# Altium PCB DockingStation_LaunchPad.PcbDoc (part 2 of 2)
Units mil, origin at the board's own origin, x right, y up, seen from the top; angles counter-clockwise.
Board outline 5425 x 6950 mil, 4 copper layers (Top Layer, GND, Power, Bottom Layer), stack 58.4 mil thick; 172 components, 183 nets, 692 pads, 746 vias.
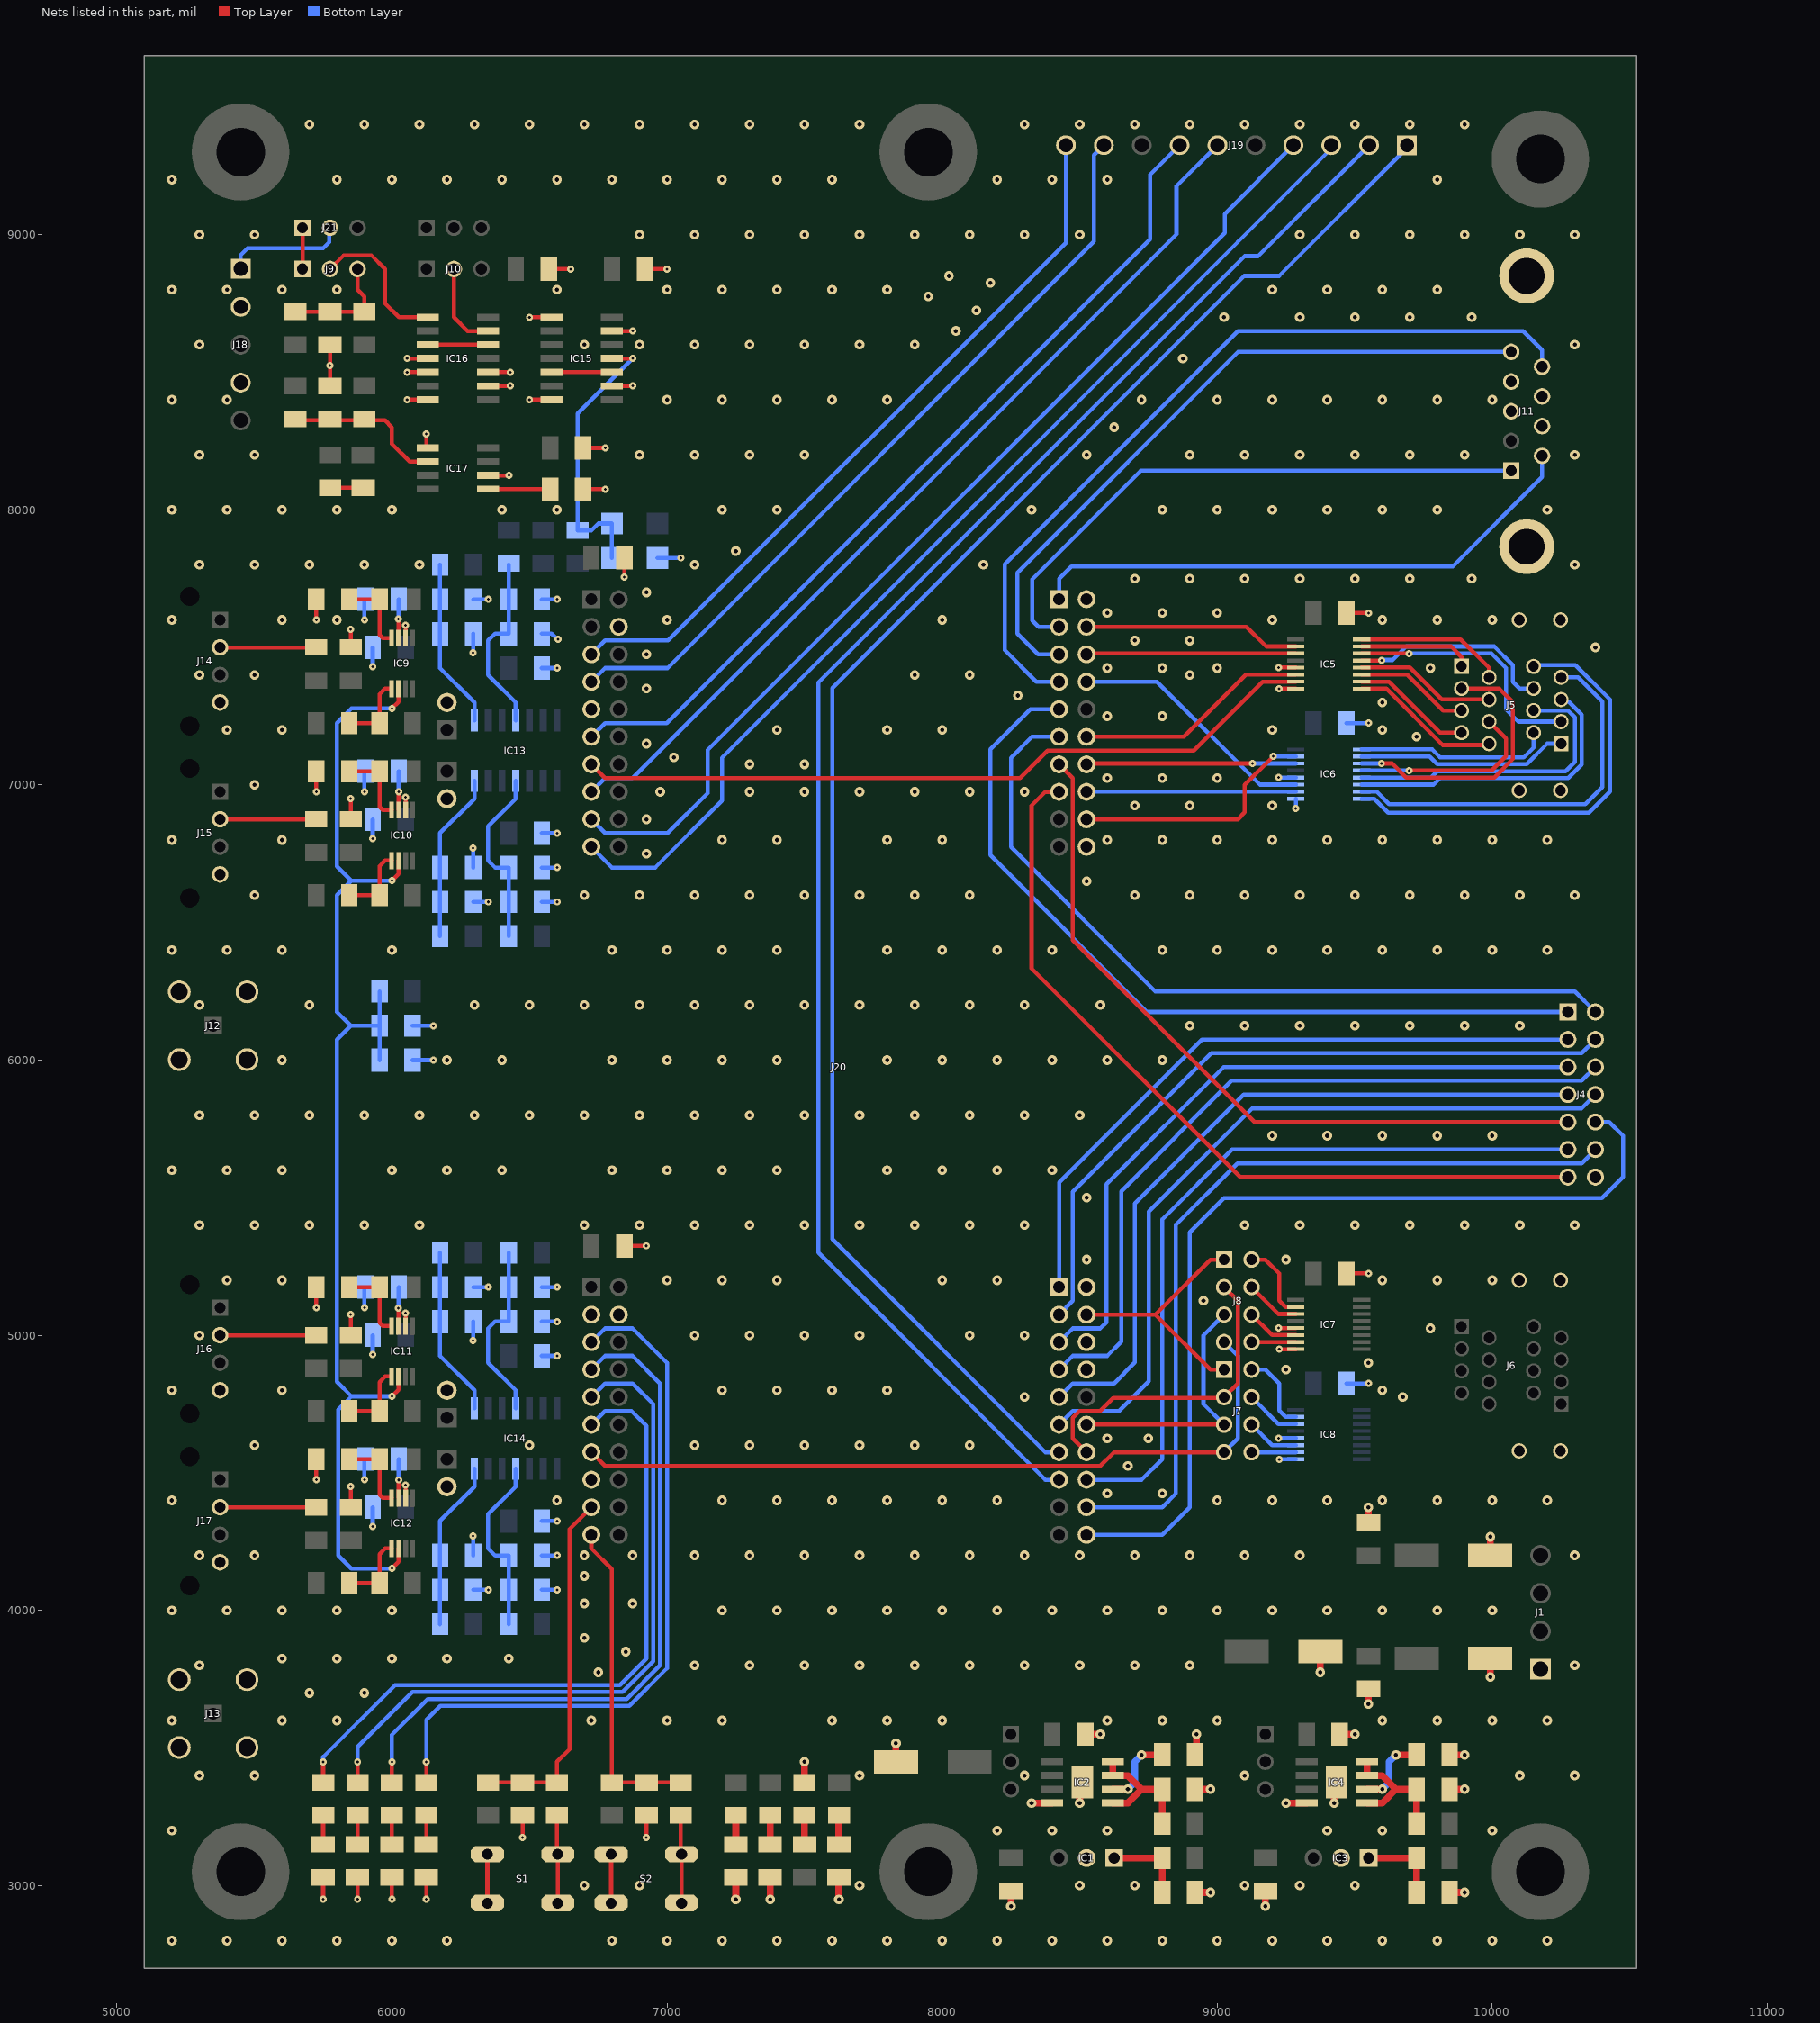
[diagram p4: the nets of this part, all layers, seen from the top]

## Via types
v1: diameter 35, hole 15, Top Layer to Bottom Layer, tented both sides, 433 vias
v2: diameter 35, hole 15, Top Layer to Bottom Layer, tented top, 166 vias
v3: diameter 26, hole 10, Top Layer to Bottom Layer, tented top, 146 vias
v4: diameter 26, hole 10, Top Layer to Bottom Layer, tented both sides, 1 vias

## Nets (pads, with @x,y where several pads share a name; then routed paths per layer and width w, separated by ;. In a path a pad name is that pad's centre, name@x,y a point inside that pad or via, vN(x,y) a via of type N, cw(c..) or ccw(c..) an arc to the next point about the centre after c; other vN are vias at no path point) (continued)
GND: +3.3V.1 +5V.1 +15V.1 C1_1.2 C2_1.2 C2_2.2 C2_3.2 C2_4.2 C3.1 C4.1 C5.2 C6.2 C8.2 C9.2 C10.2 C11.2 C12.2 C14.2 C16.2 C17.2 C18.2 C19.2 C20.2 C22.2 C23.2 C24.2 C25.2 C26.2 C27.2 C28.2 C29.2 C30.2 C31.2 C32.2 C33.2 C34.1 C35.2 C36.1 C37.2 C38.2 C39.2 C40.2 C41.2 C42.2 C43.2 C44.2 Cn_1.2 Cn_2.2 Cn_3.2 Cn_4.2 Cp_1.2 Cp_2.2 Cp_3.2 Cp_4.2 D2.2 IC1.2 IC2.4 IC2.9 IC3.2 IC4.4 IC4.9 IC5.5 IC5.8 IC6.9 IC6.12 IC7.5 IC7.8 IC8.9 IC8.12 IC9.6 IC10.6 IC11.6 IC12.6 IC15.1 IC15.7 IC15.9 IC15.13 IC16.4 IC16.5 IC16.7 IC16.9 IC16.10 IC17.1 IC17.6 J1.1 J4.14 J5.18 J5.19 J5.20 J5.21 J6.18 J6.19 J6.20 J6.21 J11.3 J11.4 J11.7 J11.8 J11.10 J12.2 J12.3 J12.4 J12.5 J13.2 J13.3 J13.4 J13.5 J14.3 J15.3 J16.3 J17.3 J18.2 J18.4 J20.20 J20.22 J20.60 J20.62 LED_0.1 LED_1.1 LED_2.1 LED_3.1 R2.2 R3_1.2 R3_2.2 R3_3.2 R3_4.2 R6_1.2 Rm_1.2 Rm_2.2 Rm_3.2 Rm_4.2 Rn2_1.1 Rn2_2.1 Rn2_3.1 Rn2_4.1 Rp2_1.1 Rp2_2.1 Rp2_3.1 Rp2_4.1 S1.3 S1.4 S2.3 S2.4 T1.2 T2.2 T3.2 T4.2 | length 7417.3
  Top Layer w15: v3(5725,4475) R3_4.2@5725,4550 ; v3(5725,5100) R3_3.2@5725,5175 ; v3(5725,6975) R3_2.2@5725,7050 ; v3(5725,7600) R3_1.2@5725,7675 ; v3(5750,2950) LED_3.1@5750,3030 ; C32.2@5775,8450 v3(5775,8525) C31.2@5775,8600 ; Rm_4.2@5850,4375 v3(5850,4450) ; Rm_3.2@5850,5000 v3(5850,5075) ; Rm_2.2@5850,6875 v3(5850,6950) ; Rm_1.2@5850,7500 v3(5850,7565) ; v3(5875,2950) LED_2.1@5875,3030 ; v3(6000,2950) LED_1.1@6000,3030 ; IC11.6@6049.41,5033.5 6050,5034.09 v3(6050,5080) ; IC9.6@6049.41,7533.5 6050,7534.09 v3(6050,7580) ; IC12.6@6050,4408.5 v3(6050,4455) ; IC10.6@6050,6908.5 v3(6050,6955) ; v3(6055,8400) IC16.7@6130,8400 ; v3(6055,8500) IC16.5@6130,8500 ; v3(6055,8550) IC16.4@6130,8550 ; v3(6125,2950) LED_0.1@6125,3030 ; v3(6125,8275) 6125,8230 IC17.1@6130,8225 ; S1.3@6347,2936 S1.4@6347,3114 ; IC17.6@6350,8125 v3(6425,8125) ; IC16.9@6350,8450 v3(6430,8450) ; IC16.10@6350,8500 v3(6430,8500) ; v3(6475,3175) C41.2@6475,3255 ; v3(6500,8400) IC15.7@6580,8400 ; v3(6500,8700) IC15.1@6580,8700 ; C38.2@6570,8875 v3(6650,8875) ; C40.2@6695,8075 v3(6775,8075) ; C39.2@6695,8225 v3(6775,8225) ; S2.3@6797,2936 S2.4@6797,3114 ; IC15.9@6800,8450 v3(6875,8450) ; IC15.13@6800,8650 v3(6875,8650) ; C44.2@6845,5325 v3(6925,5325) ; v3(6845,7755) C43.2@6845,7825 ; C37.2@6920,8875 v3(7000,8875) ; v3(6925,3175) C42.2@6925,3255 ; v3(9223.23,7426.77) IC5.5@9285.5,7426.77 ; v3(9223.82,5026.18) IC7.5@9285.5,5026.18 ; v3(9225,7350) IC5.8@9285.5,7350 ; v3(9225.59,4949.41) IC7.8@9285.5,4949.41 ; C25.2@9470,5225 v3(9550,5225) ; C23.2@9470,7625 v3(9550,7625)
  Top Layer w25: v2(7250,2950) +3.3V.1@7250,3030 ; v2(7375,2950) +5V.1@7375,3030 ; R2.2@7500,3375 v2(7500,3450) ; v2(7625,2950) +15V.1@7625,3030 ; C14.2@7832.28,3450 v2(7832.28,3517.72) ; v2(8250,2925) C9.2@8250,2980 ; v2(8325,3300) IC2.4@8400,3300 ; v2(8500,3300) 8500,3365.43 IC2.9@8509.76,3375.2 ; C12.2@8520,3550 v2(8575,3550) ; C8.2@8920,2975 v2(8975,2975) ; C10.2@8920,3350 v2(8975,3350) ; C11.2@8920,3475 8925,3480 v2(8925,3550) ; v2(9175,2925) C17.2@9175,2980 ; v2(9250,3300) IC4.4@9325,3300 ; v2(9375,3775) C22.2@9375,3850 ; v2(9425,3300) 9425,3365.43 IC4.9@9434.76,3375.2 ; C20.2@9445,3550 v2(9500,3550) ; v2(9550,3660) C5.2@9550,3715 ; C3.1@9550,4320 v2(9550,4375) ; C16.2@9845,2975 v2(9900,2975) ; C18.2@9845,3350 v2(9900,3350) ; C19.2@9845,3475 v2(9900,3475) ; v2(9992.72,3757.28) C6.2@9992.72,3825 ; C4.1@9992.72,4200 v2(9992.72,4267.72)
  Bottom Layer w15: v3(5900,4475) 5900,4545 C2_4.2@5905,4550 ; v3(5900,5100) 5900,5170 C2_3.2@5905,5175 ; v3(5900,6975) 5900,7045 C2_2.2@5905,7050 ; v3(5900,7600) 5900,7670 C2_1.2@5905,7675 ; v3(5930,4305) C30.2@5930,4375 ; v3(5930,4930) C29.2@5930,5000 ; v3(5930,6805) C28.2@5930,6875 ; v3(5930,7430) C27.2@5930,7500 ; C1_1.2@6075,6000 v3(6150,6000) ; R6_1.2@6075,6125 v3(6150,6125) ; Rp2_4.1@6295,4075 v3(6350,4075) ; Cp_4.2@6295,4200 v3(6295,4270) ; v3(6295,4980) Cn_3.2@6295,5050 ; Rn2_3.1@6295,5175 v3(6350,5175) ; Rp2_2.1@6295,6575 v3(6350,6575) ; Cp_2.2@6295,6700 v3(6295,6770) ; v3(6295,7480) Cn_1.2@6295,7550 ; Rn2_1.1@6295,7675 v3(6350,7675) ; Rn2_4.1@6545,4075 v3(6600,4075) ; Cn_4.2@6545,4200 v3(6600,4200) ; C35.2@6545,4325 v3(6600,4325) ; C36.1@6545,4925 v3(6600,4925) ; Cp_3.2@6545,5050 v3(6600,5050) ; Rp2_3.1@6545,5175 v3(6600,5175) ; Rn2_2.1@6545,6575 v4(6600,6575) ; Cn_2.2@6545,6700 v3(6600,6700) ; C33.2@6545,6825 v3(6600,6825) ; C34.1@6545,7425 v3(6600,7425) ; Cp_1.2@6545,7550 6580.46,7550 6600.96,7529.5 v3(6603.94,7529.5) ; Rp2_1.1@6545,7675 v3(6600,7675) ; D2.2@6965.35,7825 v3(7050,7825) ; v3(9223.23,7026.77) IC6.12@9285.5,7026.77 ; v3(9223.82,4626.18) IC8.12@9285.5,4626.18 ; v3(9225.59,4549.41) IC8.9@9285.5,4549.41 ; v3(9285.5,6914.5) IC6.9@9285.5,6950 ; C26.2@9470,4825 v3(9550,4825) ; C24.2@9470,7225 v3(9550,7225)
  other v1: 5200,2800 5400,2800 5600,2800 5800,2800 6000,2800 6200,2800 6800,2800 7000,2800 7200,2800 7400,2800 7600,2800 7800,2800 8000,2800 8200,2800 8400,2800 8600,2800 8800,2800 9000,2800 9200,2800 9400,2800 9600,2800 9800,2800 10000,2800 10200,2800 6700,3000 6900,3000 7700,3000 8500,3000 8700,3000 9100,3000 9300,3000 9500,3000 5200,3200 8200,3200 8400,3200 8600,3200 9400,3200 9600,3200 10000,3200 5300,3400 5500,3400 7700,3400 8300,3400 9100,3400 10100,3400 10300,3400 5200,3600 5600,3600 5800,3600 7000,3600 7200,3600 7600,3600 7800,3600 8000,3600 8600,3600 8800,3600 9000,3600 9600,3600 9800,3600 10000,3600 10200,3600 5300,3800 7100,3800 7300,3800 7500,3800 7700,3800 7900,3800 8100,3800 8300,3800 8500,3800 8700,3800 8900,3800 10300,3800 5200,4000 5400,4000 5600,4000 5800,4000 6000,4000 7200,4000 7400,4000 7600,4000 7800,4000 8000,4000 8200,4000 8400,4000 8600,4000 8800,4000 9000,4000 9200,4000 9400,4000 9600,4000 9800,4000 10000,4000 5300,4200 5500,4200 6700,4200 7100,4200 7300,4200 7500,4200 7700,4200 7900,4200 8100,4200 8300,4200 8500,4200 8700,4200 8900,4200 9100,4200 9300,4200 10300,4200 5200,4400 6600,4400 7200,4400 7400,4400 7600,4400 7800,4400 8000,4400 8200,4400 9000,4400 9200,4400 9400,4400 9600,4400 9800,4400 10000,4400 10200,4400 5500,4600 6500,4600 7100,4600 7300,4600 7500,4600 7700,4600 7900,4600 8100,4600 5200,4800 5600,4800 7200,4800 7400,4800 7600,4800 7800,4800 9600,4800 5300,5000 7100,5000 7300,5000 7500,5000 7700,5000 8100,5000 8300,5000 5400,5200 5600,5200 7000,5200 7200,5200 7400,5200 8000,5200 8200,5200 9600,5200 9800,5200 10000,5200 5300,5400 5500,5400 5700,5400 5900,5400 6100,5400 6700,5400 6900,5400 7100,5400 7300,5400 7500,5400 7700,5400 7900,5400 8100,5400 8300,5400 9100,5400 9300,5400 9500,5400 9700,5400 9900,5400 10100,5400 10300,5400 5200,5600 5400,5600 5600,5600 6000,5600 6200,5600 6400,5600 6800,5600 7000,5600 7200,5600 7400,5600 7800,5600 8000,5600 8200,5600 8400,5600 5300,5800 5500,5800 5700,5800 5900,5800 6100,5800 6300,5800 6500,5800 6700,5800 6900,5800 7100,5800 7300,5800 7500,5800 7700,5800 7900,5800 8100,5800 8300,5800 8500,5800 5600,6000 6200,6000 6400,6000 6800,6000 7000,6000 7200,6000 7400,6000 7800,6000 8000,6000 8200,6000 8400,6000 8600,6000 8800,6000 5300,6200 5700,6200 6300,6200 6500,6200 6700,6200 6900,6200 7100,6200 7300,6200 7500,6200 7700,6200 7900,6200 8100,6200 8300,6200 5200,6400 5400,6400 5600,6400 6000,6400 6800,6400 7000,6400 7200,6400 7400,6400 7800,6400 8000,6400 8200,6400 8400,6400 8800,6400 9000,6400 9200,6400 9400,6400 9600,6400 9800,6400 10000,6400 10200,6400 5500,6600 6700,6600 6900,6600 7100,6600 7300,6600 7500,6600 7700,6600 7900,6600 8100,6600 8700,6600 8900,6600 9100,6600 9300,6600 9500,6600 9700,6600 9900,6600 10100,6600 10300,6600 5200,6800 5600,6800 7200,6800 7400,6800 7800,6800 8000,6800 8600,6800 8800,6800 9000,6800 9200,6800 9400,6800 9600,6800 9800,6800 10000,6800 10200,6800 5500,7000 5400,7200 5600,7200 7400,7200 7800,7200 8000,7200 9200,7200 9600,7200 5300,7400 5500,7400 7900,7400 8100,7400 8900,7400 5200,7600 5600,7600 5800,7600 7000,7600 8000,7600 9200,7600 9600,7600 9800,7600 10000,7600 5300,7800 5500,7800 5700,7800 5900,7800 6100,7800 7100,7800 10300,7800 5200,8000 5400,8000 5600,8000 5800,8000 6000,8000 6400,8000 6600,8000 7200,8000 7400,8000 8800,8000 9000,8000 9200,8000 9400,8000 9600,8000 9800,8000 10200,8000 5300,8200 5500,8200 6900,8200 7100,8200 7300,8200 7500,8200 8900,8200 9100,8200 9300,8200 9500,8200 9700,8200 9900,8200 10300,8200 5200,8400 5400,8400 7000,8400 7200,8400 7400,8400 7600,8400 7800,8400 9000,8400 9200,8400 9400,8400 9600,8400 9800,8400 10000,8400 5300,8600 6700,8600 6900,8600 7100,8600 7300,8600 7500,8600 7700,8600 7900,8600 10300,8600 5200,8800 5400,8800 5600,8800 5800,8800 6600,8800 7000,8800 7200,8800 7400,8800 7600,8800 7800,8800 9200,8800 9400,8800 9600,8800 9800,8800 5300,9000 5500,9000 6900,9000 7100,9000 7300,9000 7500,9000 7700,9000 7900,9000 8100,9000 8300,9000 8500,9000 9300,9000 9500,9000 9700,9000 9900,9000 10100,9000 10300,9000 5200,9200 5800,9200 6000,9200 6200,9200 6400,9200 6600,9200 6800,9200 7000,9200 7200,9200 7400,9200 7600,9200 8200,9200 8400,9200 8600,9200 9800,9200 5700,9400 5900,9400 6100,9400 6300,9400 6500,9400 6700,9400 6900,9400 7100,9400 7300,9400 7500,9400 7700,9400 8300,9400 8500,9400 8700,9400 8900,9400 9100,9400 9300,9400 9500,9400 9700,9400 9900,9400
  other v2: 6725,3600 5700,3700 5900,3700 6750,3775 5600,3825 5800,3825 6000,3825 6200,3825 6425,3825 6850,3850 6700,3900 6700,4025 6875,4025 6700,4125 6875,4200 8600,4425 8800,4425 8675,4525 8600,4625 8750,4625 8300,4775 9675,4775 9250,4875 9550,4900 9775,5025 8950,5125 8525,5275 9250,5275 8525,5500 9200,5725 9400,5725 9600,5725 9800,5725 10000,5725 8900,6125 9100,6125 9300,6125 9500,6125 9700,6125 9900,6125 10100,6125 8575,6200 8525,6650 6925,6750 6925,6875 8700,6925 8900,6925 9200,6925 6975,6975 7300,6975 7500,6975 7700,6975 7900,6975 8100,6975 8300,6975 8600,7025 8800,7025 9000,7025 7300,7075 7500,7075 7025,7100 6925,7150 9725,7175 8600,7250 8800,7250 9600,7300 8275,7325 6925,7350 8600,7425 8800,7425 9000,7425 9775,7425 6925,7475 10375,7500 8700,7525 8900,7525 8600,7625 8800,7625 9000,7625 6925,7700 8700,7750 8900,7750 9100,7750 9300,7750 9500,7750 9700,7750 9925,7750 8150,7800 7250,7850 8325,8000 8525,8200 8625,8300 8725,8400 8875,8550 8050,8650 9025,8700 9300,8700 9500,8700 9700,8700 9925,8700 8125,8725 7950,8775 8175,8825 8025,8850
GPIO_COM0: J4.1 J20.36 | length 3030.9
  Bottom Layer w15: J20.36@8425,7275 8320.38,7275 8175,7129.62 8175,6745.08 8745.08,6175 J4.1@10275,6175
GPIO_COM1: J4.2 J20.35 | length 2903.6
  Bottom Layer w15: J20.35@8425,7175 8326.71,7175 8250,7098.29 8250,6775 8775,6250 10300,6250 J4.2@10375,6175
GPIO_COM2: J4.3 J20.80 | length 2445.5
  Bottom Layer w15: J20.80@8425,5175 8425,5555.19 8944.81,6075 J4.3@10275,6075
GPIO_COM3: J4.4 J20.79 | length 2596.5
  Bottom Layer w15: J20.79@8425,5075 8475.02,5125.02 8475.02,5521.57 8978.45,6025 10325,6025 J4.4@10375,6075
GPIO_COM4: J4.5 J20.78 | length 2557.9
  Bottom Layer w15: J20.78@8425,4975 8475,5025 8575,5025 8597.53,5047.53 8597.53,5548.97 9023.56,5975 J4.5@10275,5975
GPIO_COM5: J4.6 J20.77 | length 2726.4
  Bottom Layer w15: J20.77@8425,4875 8475,4925 8600,4925 8651.08,4976.08 8651.08,5523.58 9052.5,5925 10325,5925 J4.6@10375,5975
GPIO_COM6: J4.7 J20.76 | length 2644.3
  Bottom Layer w15: J20.76@8425,4775 8475.02,4825.02 8625.02,4825.02 8700.98,4900.98 8700.98,5479.07 9096.91,5875 J4.7@10275,5875
GPIO_COM7: J4.8 J20.75 | length 2808.3
  Bottom Layer w15: J20.75@8425,4675 8475,4725 8643.8,4725 8751.5,4832.7 8751.5,5449.41 9127.09,5825 10325,5825 J4.8@10375,5875
GPIO_COM8: J4.9 J20.34 | length 2733.6
  Top Layer w15: J20.34@8425,7075 8475,7025 8475,6435.79 9135.79,5775 J4.9@10275,5775
GPIO_COM9: J4.10 J20.51 | length 3344.4
  Bottom Layer w15: J20.51@8525,4275 8800,4275 8900,4375 8900,5373.97 9024.73,5498.69 10398.69,5498.69 10475,5575 10475,5725 10425,5775 J4.10@10375,5775
GPIO_COM10: J4.11 J20.53 | length 2757.2
  Bottom Layer w15: J20.53@8525,4475 8725,4475 8800,4550 8800,5420.93 9054.07,5675 J4.11@10275,5675
GPIO_COM11: J4.12 J20.52 | length 2960.5
  Bottom Layer w15: J20.52@8525,4375 8800,4375 8850,4425 8850,5401.58 9073.42,5625 10325,5625 J4.12@10375,5675
GPIO_COM12: J4.13 J20.33 | length 2976.8
  Top Layer w15: J20.33@8425,6975 8375,6975 8325,6925 8325,6332.74 9082.74,5575 J4.13@10275,5575
Master_Enable: J9.1 J21.1 | length 150.5
  Top Layer w15: J9.1@5675,8875 5674.41,8875.59 5675,8876.18 J21.1@5675,9025
MCLK+: IC5.10 J5.A7 | length 440
  Top Layer w15: IC5.10@9525,7375.59 9624.41,7375.59 9809.84,7190.16 J5.A7@9888.19,7190.16
MCLK-: IC5.9 J5.A8 | length 550.1
  Top Layer w15: IC5.9@9525,7350 9614.64,7350 9819.55,7145.1 9983.29,7145.1 J5.A8@9988.19,7150
MI+: IC6.3 J5.A3 | length 1013.1
  Top Layer w15: v3(9597.05,7077.95) 9635.73,7077.95 9686.82,7026.86 10007.49,7026.86 10075,7094.37 10075,7300.79 10025,7350.79 J5.A3@9888.19,7350.79
  Bottom Layer w15: IC6.3@9525,7077.95 v3(9597.05,7077.95)
MI-: IC6.4 J5.A6 | length 697.9
  Top Layer w15: v3(9697.64,7052.36) 9997.64,7052.36 10050,7104.72 10050,7168.5 J5.A6@9988.19,7230.31
  Bottom Layer w15: IC6.4@9525,7052.36 v3(9697.64,7052.36)
MO+: IC5.11 J5.A5 | length 417.3
  Top Layer w15: IC5.11@9525,7401.18 9690.24,7401.18 9820.94,7270.47 J5.A5@9888.19,7270.47
MO-: IC5.12 J5.A4 | length 522
  Top Layer w15: IC5.12@9525,7426.77 9700,7426.77 9816.14,7310.63 J5.A4@9988.19,7310.63 J5.A4@9980.61,7318.21
MSS+: IC5.15 J5.A1 | length 413.3
  Top Layer w15: IC5.15@9525,7503.54 9850,7503.54 9888.19,7465.35 J5.A1@9888.19,7431.1
MSS-: IC5.16 J5.A2 | length 541.2
  Top Layer w15: IC5.16@9525,7529.13 9885.43,7529.13 9988.19,7426.38 J5.A2@9988.19,7390.94
Net+3.3V_2: +3.3V.2 R5.2 | length 105
  Top Layer w25: +3.3V.2@7250,3150 R5.2@7250,3255
Net+5V_2: +5V.2 R4.2 | length 105
  Top Layer w25: +5V.2@7375,3150 R4.2@7375,3255
Net+15V_2: +15V.2 R3.2 | length 105
  Top Layer w25: +15V.2@7625,3150 R3.2@7625,3255
Net-15V_2: -15V.2 R2.1 | length 105
  Top Layer w25: -15V.2@7500,3150 R2.1@7500,3255
NetC2_1_1: C2_1.1 IC9.7 | length 142
  Top Layer w15: IC9.7@6023.82,7533.5 v3(6023.82,7603.82)
  Bottom Layer w15: v3(6023.82,7603.82) 6023.82,7673.82 C2_1.1@6025,7675
NetC2_2_1: C2_2.1 IC10.7 | length 141.7
  Top Layer w15: IC10.7@6024.41,6908.5 v3(6024.41,6974.41)
  Bottom Layer w15: v3(6024.41,6974.41) 6024.41,7049.41 C2_2.1@6025,7050
NetC2_3_1: C2_3.1 IC11.7 | length 142
  Top Layer w15: IC11.7@6023.82,5033.5 v3(6023.82,5098.82)
  Bottom Layer w15: v3(6023.82,5098.82) 6023.82,5173.82 C2_3.1@6025,5175
NetC2_4_1: C2_4.1 IC12.7 | length 141.7
  Top Layer w15: IC12.7@6024.41,4408.5 v3(6024.41,4474.41)
  Bottom Layer w15: v3(6024.41,4474.41) 6024.41,4549.41 C2_4.1@6025,4550
NetC8_1: C8.1 IC1.1 R6.2 | length 300
  Top Layer w25: IC1.1@8625,3100 R6.2@8800,3100 C8.1@8800,2975
NetC10_1: C10.1 IC2.5 IC2.7 IC2.8 R7.1 | length 501.4
  Top Layer w25: IC2.5@8620,3300 8675,3300 8725,3350 ; IC2.8@8620,3450 IC2.7@8620,3400 8675,3400 8725,3350 ; R7.1@8800,3225 C10.1@8800,3350 8725,3350
NetC11_1: C11.1 IC2.6 | length 275.7
  Top Layer w25: IC2.6@8620,3350 v2(8675,3350) ; v2(8725,3475) C11.1@8800,3475
  Bottom Layer w25: v2(8675,3350) 8700,3375 8700,3450 v2(8725,3475)
NetC16_1: C16.1 IC3.1 R8.2 | length 300
  Top Layer w25: IC3.1@9550,3100 R8.2@9725,3100 C16.1@9725,2975
NetC18_1: C18.1 IC4.5 IC4.7 IC4.8 R9.1 | length 501.4
  Top Layer w25: IC4.5@9545,3300 9600,3300 9650,3350 ; IC4.8@9545,3450 IC4.7@9545,3400 9600,3400 9650,3350 ; R9.1@9725,3225 C18.1@9725,3350 9650,3350
NetC19_1: C19.1 IC4.6 | length 275.7
  Top Layer w25: IC4.6@9545,3350 v2(9600,3350) ; v2(9650,3475) C19.1@9725,3475
  Bottom Layer w25: v2(9600,3350) 9625,3375 9625,3450 v2(9650,3475)
NetC40_1: C40.1 IC17.5 | length 225
  Top Layer w15: IC17.5@6350,8075 C40.1@6575,8075
NetCn_1_1: Cn_1.1 IC13.8 Rn1_1.1 Rn2_1.2 | length 616.8
  Bottom Layer w15: Rn1_1.1@6175,7800 Rn2_1.2@6175,7675 Cn_1.1@6175,7550 6175,7425 6300,7300 IC13.8@6300,7235
NetCn_2_1: Cn_2.1 IC13.4 Rn1_2.1 Rn2_2.2 | length 666.8
  Bottom Layer w15: Rn1_2.1@6425,6450 Rn2_2.2@6425,6575 Cn_2.1@6425,6700 6375,6700 6350,6725 6350,6850 6450,6950 IC13.4@6450,7015
NetCn_3_1: Cn_3.1 IC14.8 Rn1_3.1 Rn2_3.2 | length 616.8
  Bottom Layer w15: Rn1_3.1@6175,5300 Rn2_3.2@6175,5175 Cn_3.1@6175,5050 6175,4925 6300,4800 IC14.8@6300,4735
NetCn_4_1: Cn_4.1 IC14.4 Rn1_4.1 Rn2_4.2 | length 666.8
  Bottom Layer w15: Rn1_4.1@6425,3950 Rn2_4.2@6425,4075 Cn_4.1@6425,4200 6375,4200 6350,4225 6350,4350 6450,4450 IC14.4@6450,4515
NetCp_1_1: Cp_1.1 IC13.11 Rp1_1.1 Rp2_1.2 | length 666.8
  Bottom Layer w15: Rp1_1.1@6425,7800 Rp2_1.2@6425,7675 Cp_1.1@6425,7550 6375,7550 6350,7525 6350,7400 6450,7300 IC13.11@6450,7235
NetCp_2_1: Cp_2.1 IC13.7 Rp1_2.1 Rp2_2.2 | length 616.8
  Bottom Layer w15: Rp1_2.1@6175,6450 Rp2_2.2@6175,6575 Cp_2.1@6175,6700 6175,6712.5 6175,6825 6300,6950 IC13.7@6300,7015
NetCp_3_1: Cp_3.1 IC14.11 Rp1_3.1 Rp2_3.2 | length 666.8
  Bottom Layer w15: Rp1_3.1@6425,5300 Rp2_3.2@6425,5175 Cp_3.1@6425,5050 6375,5050 6350,5025 6350,4900 6450,4800 IC14.11@6450,4735
NetCp_4_1: Cp_4.1 IC14.7 Rp1_4.1 Rp2_4.2 | length 616.8
  Bottom Layer w15: Rp1_4.1@6175,3950 Rp2_4.2@6175,4075 Cp_4.1@6175,4200 6175,4212.5 6175,4325 6300,4450 IC14.7@6300,4515
NetD1_2: D1.2 D2.1 IC15.11 R15.2 | length 1043.2
  Top Layer w15: IC15.11@6800,8550 v3(6875,8550)
  Bottom Layer w15: D2.1@6800,7825 D1.2@6800,7950 6750,7950 6725,7925 R15.2@6675,7925 6675,8350 v3(6875,8550)
NetIC9_1: IC9.1 R1_1.1 R2_1.2 | length 266.1
  Top Layer w15: R1_1.1@5845,7225 R2_1.2@5955,7225 5955,7330 5975,7350 IC9.1@5997.82,7350
NetIC9_8: IC9.8 R3_1.1 R4_1.1 | length 294.3
  Top Layer w15: R3_1.1@5849.48,7670.52 R3_1.1@5845,7675 R4_1.1@5955,7675 5955,7545 5966.5,7533.5 IC9.8@5998.23,7533.5
NetIC10_1: IC10.1 R1_2.1 R2_2.2 | length 267.1
  Top Layer w15: R1_2.1@5845,6600 R2_2.2@5955,6600 5955,6705 5975,6725 IC10.1@5998.82,6725
NetIC10_8: IC10.8 R3_2.1 R4_2.1 | length 288.6
  Top Layer w15: R3_2.1@5845,7050 R4_2.1@5955,7050 5955,6920 5966.5,6908.5 IC10.8@5998.82,6908.5
NetIC11_1: IC11.1 R1_3.1 R2_3.2 | length 266.5
  Top Layer w15: R1_3.1@5845,4725 R2_3.2@5955,4725 5955,4830 5975,4850 IC11.1@5998.23,4850
NetIC11_8: IC11.8 R3_3.1 R4_3.1 | length 288
  Top Layer w15: R3_3.1@5845,5175 R4_3.1@5955,5175 5955,5045 5966.5,5033.5 IC11.8@5998.23,5033.5
NetIC12_1: IC12.1 R1_4.1 R2_4.2 | length 267.1
  Top Layer w15: R1_4.1@5845,4100 R2_4.2@5955,4100 5955,4205 5975,4225 IC12.1@5998.82,4225
NetIC12_8: IC12.8 R3_4.1 R4_4.1 | length 288.6
  Top Layer w15: R3_4.1@5845,4550 R4_4.1@5955,4550 5955,4420 5966.5,4408.5 IC12.8@5998.82,4408.5
NetIC15_5: IC15.5 IC15.10 | length 220
  Top Layer w15: IC15.5@6580,8500 IC15.10@6800,8500
NetIC16_1: IC16.1 J9.2 | length 542.1
  Top Layer w15: J9.2@5775,8875 5825,8925 5925,8925 5975,8875 5975,8750 6025,8700 IC16.1@6130,8700
NetIC16_3: IC16.3 IC16.12 | length 220
  Top Layer w15: IC16.3@6130,8600 IC16.12@6350,8600
NetIC16_13: IC16.13 J10.2 | length 320.7
  Top Layer w15: J10.2@6225,8875 6225,8700 6275,8650 IC16.13@6350,8650
NetJ18_1: J18.1 J21.2 | length 445.1
  Bottom Layer w15: J18.1@5450,8875.59 5450,8925 5475,8950 5750,8950 5772.5,8972.5 5772.5,9022.5 J21.2@5775,9025
NetLED6_2: LED6.2 R16.1 | length 120
  Top Layer w15: R16.1@5775,8080 LED6.2@5895,8080
NetLED_0_2: LED_0.2 R10.2 | length 105
  Top Layer w15: LED_0.2@6125,3150 R10.2@6125,3255
NetLED_1_2: LED_1.2 R11.2 | length 105
  Top Layer w15: LED_1.2@6000,3150 R11.2@6000,3255
NetLED_2_2: LED_2.2 R12.2 | length 105
  Top Layer w15: LED_2.2@5875,3150 R12.2@5875,3255
NetLED_3_2: LED_3.2 R13.2 | length 105
  Top Layer w15: LED_3.2@5750,3150 R13.2@5750,3255
NetR21_2: R21.2 S1.1 S1.2 | length 320.2
  Top Layer w15: R21.2@6600,3255 6600,3117 S1.2@6603,3114 S1.1@6603,2936
NetR23_2: R23.2 S2.1 S2.2 | length 320.2
  Top Layer w15: R23.2@7050,3255 7050,3117 S2.2@7053,3114 S2.1@7053,2936
P22: J19.6 J20.8 | length 3351.5
  Bottom Layer w15: J20.8@6725,6975 6775,7025 6875.12,7025 8851.91,9001.79 8851.91,9175.73 J19.6@9001.18,9325
P29: J20.11
P40: C42.1 J20.50 R23.1 R24.1 | length 1181.1
  Top Layer w15: J20.50@6725,4275 6725,4225 6800,4150 R24.1@6800,3375 C42.1@6925,3375 R23.1@7050,3375
P41: C41.1 J20.49 R21.1 R22.1 | length 1301.8
  Top Layer w15: R22.1@6350,3375 C41.1@6475,3375 R21.1@6600,3375 6600,3450 6646.41,3496.41 6646.41,4296.41 J20.49@6725,4375
P52: J20.48
P67: J20.5
P95: J20.42
P104: J19.3 J20.10 | length 3906.2
  Bottom Layer w15: J20.10@6725,6775 6800,6700 6957.28,6700 7200.79,6943.51 7200.79,7099.21 9075.79,8974.21 9414.57,9312.98 J19.3@9414.57,9325
P105: J19.4 J20.9 | length 3740.4
  Bottom Layer w15: J20.9@6725,6875 6775,6825 7002.74,6825 7147.79,6970.05 7147.79,7127.21 9027.19,9006.61 9027.19,9075.42 J19.4@9276.77,9325
P111: J19.7 J20.6 | length 3166.9
  Bottom Layer w15: J20.6@6725,7175 6775,7225 6998.88,7225 8756.5,8982.62 8756.5,9218.12 J19.7@8863.39,9325
P130: J20.57
P131: J20.58
PWM1A: J11.6 J20.40 | length 2060.8
  Bottom Layer w15: J20.40@8425,7675 8425,7750 8469.41,7794.41 9856.41,7794.41 10181,8119 J11.6@10181,8196
PWM1B: J11.1 J20.39 | length 2161.4
  Bottom Layer w15: J20.39@8425,7575 8350,7575 8327.69,7597.31 8327.69,7747.31 8722.37,8142 J11.1@10069,8142
PWM2A: J11.5 J20.38 | length 2531.6
  Bottom Layer w15: J20.38@8425,7475 8349.07,7475 8273.57,7550.5 8273.57,7771.57 9076,8574 J11.5@10069,8574
PWM2B: J11.9 J20.37 | length 2956.4
  Bottom Layer w15: J20.37@8425,7375 8342.71,7375 8227.21,7490.5 8227.21,7801.47 9075.74,8650 10112,8650 10181,8581 10181,8532 10175,8526 J11.9@10181,8520
PWM8A: J19.1 J20.74 | length 6060
  Bottom Layer w15: J20.74@8425,4575 8375,4575 7600.85,5349.15 7600.85,7352.05 9098.56,8849.77 9224.77,8849.77 9690.16,9315.16 J19.1@9690.16,9325
PWM8B: J19.2 J20.73 | length 6100.4
  Bottom Layer w15: J20.73@8425,4475 8375,4475 7549.92,5300.08 7549.92,7372.43 9099.49,8922 9149.37,8922 J19.2@9552.36,9325
PWM10A: J19.9 J20.4 | length 2854.9
  Bottom Layer w15: J20.4@6725,7375 6775,7425 7002.52,7425 8552.06,8974.54 8552.06,9289.26 J19.9@8587.8,9325
PWM10B: J19.10 J20.3 | length 2698.9
  Bottom Layer w15: J20.3@6725,7475 6775,7525 7004.37,7525 8450,8970.63 J19.10@8450,9325
SCLK+: IC6.7 J5.B7 | length 1417.3
  Bottom Layer w15: IC6.7@9525,6975.59 9579.99,6975.59 9625.4,6930.18 10337.92,6930.18 10400.57,6992.82 10400.57,7302.68 10312.31,7390.94 J5.B7@10250,7390.94
SCLK-: IC6.8 J5.B8 | length 1623.3
  Bottom Layer w15: IC6.8@9525,6950 9570.23,6950 9621.76,6898.47 10350.6,6898.47 10428.27,6976.14 10428.27,7310.34 10302.6,7436 10154.9,7436 J5.B8@10150,7431.1
Sens1: J14.4 Rs_1.1 | length 350
  Top Layer w15: J14.4@5375,7500 Rs_1.1@5725,7500
Sens2: J15.4 Rs_2.1 | length 350
  Top Layer w15: J15.4@5375,6875 Rs_2.1@5725,6875
Sens3: J16.4 Rs_3.1 | length 350
  Top Layer w15: J16.4@5375,5000 Rs_3.1@5725,5000
Sens4: J17.4 Rs_4.1 | length 350
  Top Layer w15: J17.4@5375,4375 Rs_4.1@5725,4375
SI+: IC6.6 J5.B5 | length 1110
  Bottom Layer w15: IC6.6@9525,7001.18 9786.54,7001.18 9810.36,7025 10276.57,7025 10325,7073.43 10325,7255.83 10277.87,7302.95 10257.68,7302.95 J5.B5@10250,7310.63
SI-: IC6.5 J5.B4 | length 1120.7
  Bottom Layer w15: IC6.5@9525,7026.77 9776.77,7026.77 9800,7050 10266.21,7050 10300,7083.79 10300,7245.47 10275,7270.47 J5.B4@10150,7270.47
SO+: IC5.14 J5.B3 | length 915.4
  Top Layer w15: IC5.14@9525,7477.95 v3(9697.05,7477.95)
  Bottom Layer w15: v3(9697.05,7477.95) 9997.05,7477.95 10050,7425 10050,7275 10094.68,7230.31 J5.B3@10250,7230.31
SO-: IC5.13 J5.B6 | length 745.4
  Top Layer w15: IC5.13@9525,7452.36 v3(9597.64,7452.36)
  Bottom Layer w15: v3(9597.64,7452.36) 9599.74,7454.47 9637.5,7454.47 9686.48,7503.45 10006.9,7503.45 10075,7435.36 10075,7375 10099.21,7350.79 10148.43,7350.79 10149.21,7350 J5.B6@10150,7350.79
SPIA_MCLK: IC5.7 J20.7 | length 2726.4
  Top Layer w15: J20.7@6725,7075 6775,7025 8283.04,7025 8383.04,7125 8914.99,7125 9165.58,7375.59 IC5.7@9285.5,7375.59
SPIA_MI: IC6.14 J20.14 | length 761.7
  Top Layer w15: J20.14@8525,7075 8527.95,7077.95 v3(9127.95,7077.95)
  Bottom Layer w15: v3(9127.95,7077.95) IC6.14@9285.5,7077.95
SPIA_MO: IC5.6 J20.15 | length 854.2
  Top Layer w15: J20.15@8525,7175 8878.71,7175 9104.9,7401.18 IC5.6@9285.5,7401.18
SPIA_MSS: IC5.2 J20.19 | length 790.1
  Top Layer w15: J20.19@8525,7575 9106.18,7575 9177.64,7503.54 IC5.2@9285.5,7503.54
SPIB_CLK: J7.7 J8.7 J20.47 | length 2782.8
  Top Layer w15: J20.47@6725,4575 6775,4525 8575,4525 8625,4575 J7.7@9025,4575
  Bottom Layer w15: J7.7@9025,4575 9075,4625 9075,4925 J8.7@9025,4975
SPIB_CS: J7.1 J8.1 J20.59 | length 915.7
  Top Layer w15: J20.59@8525,5075 8775,5075 ; J7.1@9025,4875 8975,4875 8775,5075 ; J8.1@9025,5275 8975,5275 8775,5075
SPIB_MCLK: IC7.7 J8.8 | length 172.7
  Top Layer w15: J8.8@9137.18,4975 J8.8@9125,4975 IC7.7@9285.5,4975
SPIB_MI: IC7.3 J8.4 | length 200.9
  Top Layer w15: J8.4@9125,5175 9222.64,5077.36 IC7.3@9285.5,5077.36
SPIB_MISO: J7.3 J8.3 J20.54 | length 1168.2
  Top Layer w15: J20.54@8525,4575 8475,4625 8475,4700 8500,4725 8575,4725 8622.5,4772.5 9022.5,4772.5 J7.3@9025,4775 9075,4825 9075,5125 J8.3@9025,5175
SPIB_MO: IC7.6 J8.6 | length 191.3
  Top Layer w15: J8.6@9125,5075 9199.41,5000.59 IC7.6@9285.5,5000.59
SPIB_MOSI: J7.5 J8.5 J20.55 | length 962.1
  Top Layer w15: J20.55@8525,4675 J7.5@9025,4675
  Bottom Layer w15: J7.5@9025,4675 8950,4750 8950,5000 J8.5@9025,5075
SPIB_MSS: IC7.2 J8.2 | length 290.1
  Top Layer w15: J8.2@9125,5275 9175,5275 9225.52,5224.48 9225.52,5125.52 9248.59,5102.45 9285,5102.45 IC7.2@9285.5,5102.95
SPIB_SCLK: IC8.10 J7.8 | length 160.5
  Bottom Layer w15: J7.8@9125,4575 IC8.10@9285.5,4575
SPIB_SI: IC8.11 J7.6 | length 191.3
  Bottom Layer w15: J7.6@9125,4675 9199.41,4600.59 IC8.11@9285.5,4600.59
SPIB_SO: IC8.14 J7.4 | length 200.9
  Bottom Layer w15: J7.4@9125,4775 9222.64,4677.36 IC8.14@9285.5,4677.36
SPIB_SSS: IC8.15 J7.2 | length 289.7
  Bottom Layer w15: J7.2@9125,4875 9175,4875 9225,4825 9225,4726.04 9248.09,4702.95 IC8.15@9285.5,4702.95
SPIC_SCLK: IC6.10 J20.13 | length 760.7
  Bottom Layer w15: J20.13@8525,6975 8525.3,6975.3 9285.2,6975.3 IC6.10@9285.5,6975.59
SPIC_SI: IC6.11 J20.17 | length 915.3
  Bottom Layer w15: J20.17@8525,7375 8780.93,7375 9154.75,7001.18 IC6.11@9285.5,7001.18
SPIC_SO: IC5.3 J20.18 | length 761.7
  Top Layer w15: J20.18@8525,7475 8527.95,7477.95 IC5.3@9285.5,7477.95
SPIC_SSS: IC6.15 J20.12 | length 913.7
  Top Layer w15: J20.12@8525,6875 9075,6875 9100.01,6900.01 9100.01,7000.01 v3(9203.54,7103.54)
  Bottom Layer w15: v3(9203.54,7103.54) IC6.15@9285.5,7103.54
SSS+: IC6.2 J5.B1 | length 767.9
  Bottom Layer w15: IC6.2@9525,7103.54 9771.46,7103.54 9800,7075 10125,7075 10200,7150 J5.B1@10250,7150
SSS-: IC6.1 J5.B2 | length 706.5
  Bottom Layer w15: IC6.1@9525,7129.13 9781.22,7129.13 9810.36,7100 10114.64,7100 10150,7135.36 J5.B2@10150,7190.16
State0: J20.43 R10.1 | length 2637.8
  Top Layer w15: R10.1@6125,3375 v3(6125,3450)
  Bottom Layer w15: v3(6125,3450) 6125,3602.39 6175.68,3653.07 6863.42,3653.07 7000,3789.64 7000,4900 6875,5025 6775,5025 J20.43@6725,4975
State1: J20.44 R11.1 | length 2589.2
  Top Layer w15: R11.1@6000,3375 v3(6000,3450)
  Bottom Layer w15: v3(6000,3450) 6000,3547.47 6130.59,3678.07 6853.07,3678.07 6975,3800 6975,4825 6875,4925 6775,4925 J20.44@6725,4875
State2: J20.45 R12.1 | length 2544.6
  Top Layer w15: R12.1@5875,3375 v3(5875,3450)
  Bottom Layer w15: v3(5875,3450) 5875,3503.7 6074.76,3703.46 6838.81,3703.46 6950,3814.64 6950,4750 6875,4825 6775,4825 J20.45@6725,4775
State3: J20.46 R13.1 | length 2511.3
  Top Layer w15: R13.1@5750,3375 v3(5750,3450)
  Bottom Layer w15: v3(5750,3450) 5750,3467.35 6011.5,3728.85 6828.85,3728.85 6925,3825 6925,4670.54 6870.54,4725 6775,4725 J20.46@6720.02,4670.02
User_Enable: C31.1 J9.3 R17.1 R18.1 | length 415.4
  Top Layer w15: R17.1@5650,8720 C31.1@5775,8720 R18.1@5900,8720 5900,8775 5875,8800 J9.3@5875,8875
USER_RESET: C32.1 IC17.2 R19.1 R20.1 | length 579.6
  Top Layer w15: R19.1@5650,8325 R20.1@5900,8325 ; R20.1@5900,8330 5905,8325 5975,8325 6000,8300 6000,8239.64 6064.64,8175 IC17.2@6130,8175
Vocm_ref: C1_1.1 IC9.2 IC10.2 IC11.2 IC12.2 R5_1.2 R6_1.1 | length 4567.8
  Top Layer w15: v3(6000,4152.34) 6024.41,4176.75 IC12.2@6024.41,4225 ; v3(6000,4777.93) 6023.82,4801.75 IC11.2@6023.82,4850 ; v3(6000,6652.34) 6024.41,6676.75 IC10.2@6024.41,6725 ; v3(6000,7277.93) 6023.82,7301.75 IC9.2@6023.82,7350
  Bottom Layer w15: C1_1.1@5955,6000 R6_1.1@5955,6125 ; R5_1.2@5955,6250 R6_1.1@5955,6125 ; v3(6000,4152.34) 5852.34,4152.34 5804.68,4200 5804.68,4729.68 5852.93,4777.93 ; v3(6000,4777.93) 5852.93,4777.93 ; v3(6000,6652.34) 5852.34,6652.34 ; v3(6000,7277.93) 5852.93,7277.93 5800,7225 5800,6704.68 5852.34,6652.34 ; 5850,6125 R6_1.1@5955,6125 ; 5850,6125 5800,6075 5800,4830.86 5852.93,4777.93 ; 5850,6125 5800,6175 5800,6600 5852.34,6652.34
pads on no net: IC15.2 IC15.8 IC15.12 IC16.6 IC16.8 IC17.7 J14.MH1 J14.MH2 J15.MH1 J15.MH2 J16.MH1 J16.MH2 J17.MH1 J17.MH2 J20.16 J20.21 J20.56 J20.61
copper on no net:
  other v2: 6850,7125

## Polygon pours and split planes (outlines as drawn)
-15V0 on Power "-15V0_L03_P044" (solid, remove dead copper, pour order 44): 6400,3550 6600,3550 6600,8075 6175,8075 6175,7975 6525,7975 6525,7775 6400,7775 6400,6975 6525,6975 6525,6675 6400,6675 6400,5450 6525,5450 6525,5200 6400,5200 6400,4475 6525,4475 6525,4175 6400,4175
+15V0 on Power "+15V0_L03_P040" (solid, remove dead copper, pour order 40): 6175,3550 6350,3550 6350,4225 6500,4225 6500,4425 6350,4425 6350,5250 6500,5250 6500,5425 6350,5425 6350,6725 6500,6725 6500,6925 6350,6925 6350,7825 6475,7825 6475,7925 6350,7925 6175,7925
3V3 on Power "3V3_L03_P036" (solid, remove dead copper, pour order 36): 9323.58,7775 9325.59,3875.15 8975,3874.81 8975,3399.99 7725,3400.01 7725,3550 7525,3550 7525,3400.01 5725.01,3400.03 5724.98,8075 6124.25,8075 6125.64,3500.01 6650,3500 6650,5125 6650,5250 6650,7625 6650,7775
5V0 on Power "5V0_L03_P034" (solid, remove dead copper, pour order 34): 9475,4150 9475,3675 9475,3400 9025,3400 9025,3825 9375,3825 9375,4350 9375,7825 6650,7825 6650,8125 5125,8125 5125.01,9624.98 10500,9625.02 10500,4500 10500,4325 10500,4150 10075,4150
-15V0 on Power "-15V0_L03_P032" (solid, remove dead copper, pour order 32): 10450.06,4125 9500,4125.01 9500,4000.58 10375.07,3999.46 10374.93,2850 7750,2850 7750,3175 6450,3175 6450,2900 6450,2850 5250,2850 5250,3250 5475,3250 5475,4350 5275,4350 5275,4650 5450,4650 5450,4975 5275,4975 5275,5950 5475,5950 5475,6850 5275,6850 5275,7150 5475,7150 5475,7475 5125.01,7475 5125,2724.86 10500,2725.12 10500,4125
+15V0 on Power "+15V0_L03_P030" (solid, remove dead copper, pour order 30): 10325,3975 9500,3975 9500,3850 9500,3349.99 7675,3350 7675,3500 7575,3500 7575,3350 5675,3350 5675,8075 5125,8075 5125,7525 5525,7525 5525,7100 5325,7100 5325,6900 5525,6900 5525,5900 5325,5900 5325,5025 5500,5025 5500,4600 5325,4600 5325,4400 5525,4400 5525,3250 5650,3250 5650,2900.01 6400,2900.01 6400,3225 7575,3225 8150,3225 8150,2900 9975,2900 9975,3275 10325,3275
GND on GND "GND_L02_P028" (solid, remove dead copper, pour order 28): 5125,9625 10500,9625 10500,2725 5125,2725
GND on Bottom Layer "GND_L04_P046" (solid, remove dead copper, pour order 46): 5125,9625 10500,9625 10500,2725 5125,2725
-15V0 on Bottom Layer "-15V0_L04_P042" (solid, remove dead copper, pour order 42): 6400,3625 6600,3625 6600,2725 6400,2725
+15V0 on Bottom Layer "+15V0_L04_P038" (solid, remove dead copper, pour order 38): 6175,3625 6350,3625 6350,2900 6175,2900

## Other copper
Top Layer:

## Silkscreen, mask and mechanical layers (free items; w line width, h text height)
Top Overlay:
  lines w6: 5990,8230 5970,8250 ; 5990,8270 5970,8250 ; 5990,8770 5970,8790 ; 5990,8810 5970,8790 ; 6060,8250 5970,8250 ; 6060,8790 5970,8790
  lines w40: 6279.91,4549.91 6280,4549.83 ; 6279.91,4699.91 6280,4699.83 ; 6279.91,7049.91 6280,7049.83 ; 6280,7200 ccw(c6270,7200) 6280,7200.17
  text "GEPE-0142" at 6190,9240 h120
  text "LAUNCHXL-F28379D" at 6490,9000 h30
Bottom Overlay:
  lines w6: 6120,7920 6140,7900 ; 6140,8070 6140,7990 6140,7900 ; 6160,7920 6140,7900 ; 6330,5400 6350,5380 ; 6350,5550 6350,5470 6350,5380 ; 6370,5400 6350,5380 ; 6600,5400 6620,5380 ; 6620,5620 6620,5470 6620,5380 ; 6640,5400 6620,5380
Mechanical 1:
  lines w15: 10100,5350 10400,5350
Board Outline:
  lines w6: 5100,2700 5100,9650 6175,9650 10525,9650 10525,2700 5100,2700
